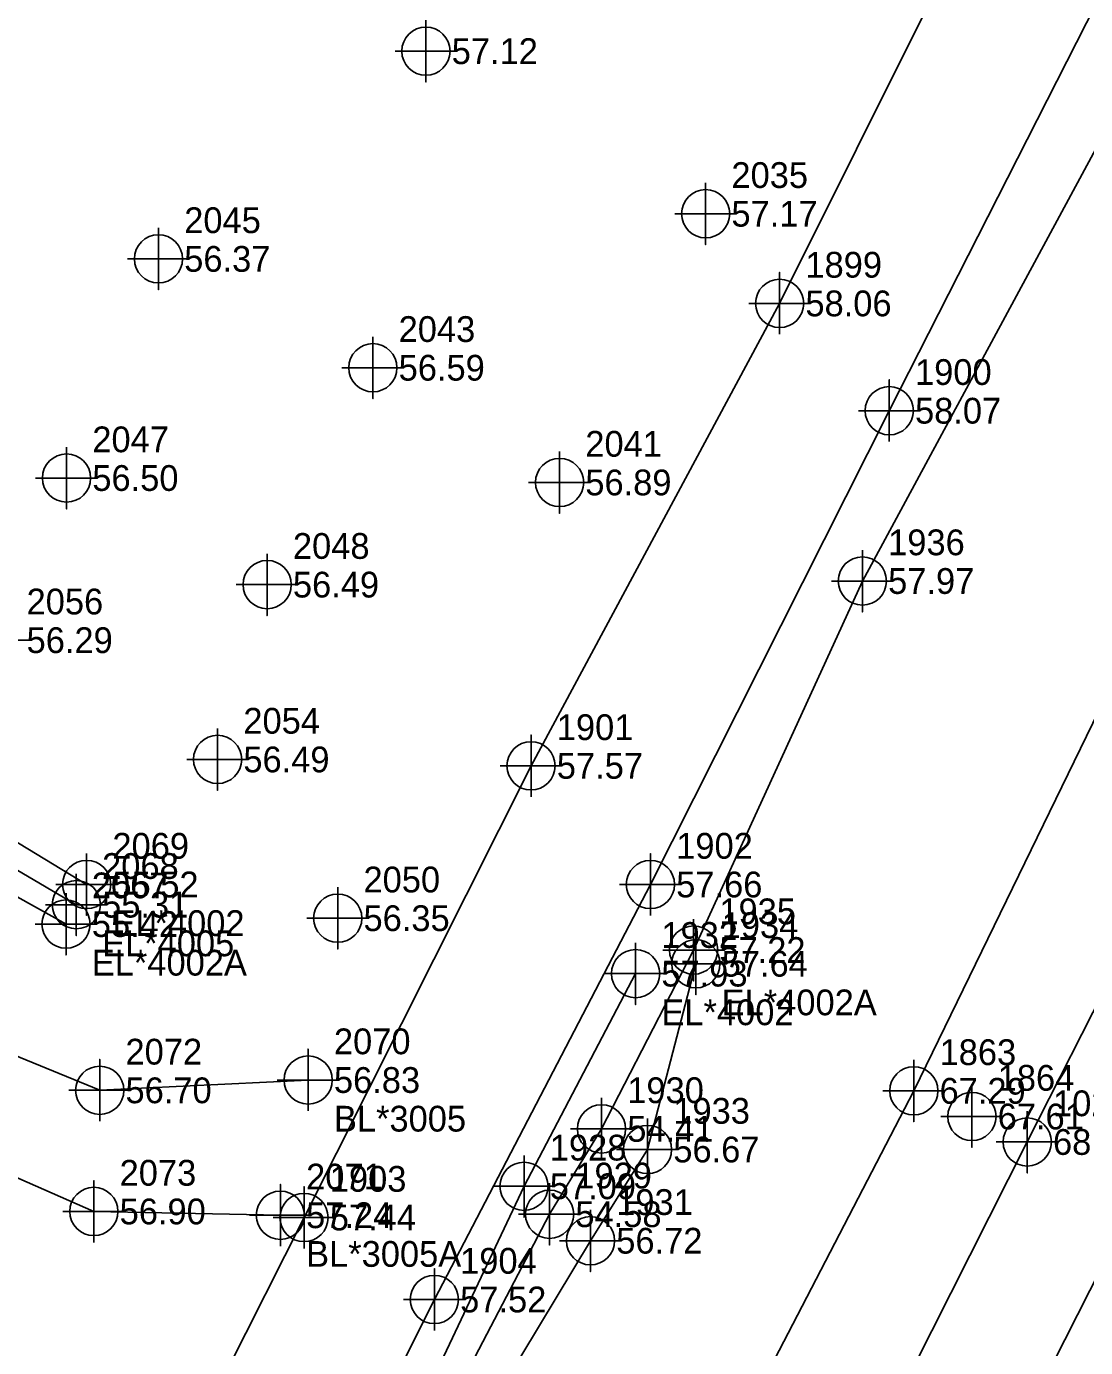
# Model space of a CAD drawing. Extents: x 2062781 to 2066835, y 358981 to 366501.
# Drawn here: x 2065986.1 to 2066088.9, y 365426.5 to 365554.7 of the extents above; entities that cross this region are included whole.
import ezdxf

# ---------------------------------------------------------------- set-up
doc = ezdxf.new("R2010")
doc.units = 0
for name, color, linetype in [('Exist DTM Breakline', 7, 'Continuous'), ('Exist DTM Breakline Cogo Comment', 7, 'Continuous'), ('Exist DTM Breakline Cogo Elevation', 7, 'Continuous'), ('Exist DTM Breakline Cogo Number', 7, 'Continuous'), ('Exist DTM Breakline Cogo Point CELL', 7, 'Continuous'), ('Exist DTM Crownline', 7, 'Continuous'), ('Exist DTM Regular Point CELL', 7, 'Continuous'), ('Exist DTM Regular Point Cogo Elevation', 7, 'Continuous'), ('Exist DTM Regular Point Cogo Number', 7, 'Continuous'), ('Exist DTM Ridgeline', 7, 'Continuous'), ('Exist DTM Ridgeline Cogo Comment', 7, 'Continuous'), ('Exist DTM Ridgeline Cogo Elevation', 7, 'Continuous'), ('Exist DTM Ridgeline Cogo Number', 7, 'Continuous'), ('Exist DTM Ridgeline Cogo Point CELL', 7, 'Continuous'), ('Exist Roads EOP', 7, 'Continuous'), ('Exist Roads EOP Cogo Elevation', 7, 'Continuous'), ('Exist Roads EOP Cogo Number', 7, 'Continuous'), ('Exist Roads EOP Cogo Point CELL', 7, 'Continuous'), ('Exist Roads Soil', 7, 'Continuous'), ('Exist Roads Soil Cogo Comment', 7, 'Continuous'), ('Exist Roads Soil Cogo Elevation', 7, 'Continuous'), ('Exist Roads Soil Cogo Number', 7, 'Continuous'), ('Exist Roads Soil Cogo Point CELL', 7, 'Continuous')]:
    doc.layers.add(name, color=color, linetype=linetype)

msp = doc.modelspace()

# ---------------------------------------------------------------- linework, layer by layer
at = {"layer": 'Exist DTM Breakline'}
for points in [[(2065868.05, 365108.36), (2065887.64, 365147.12), (2065915.95, 365200.53), (2065942.89, 365253.9), (2065967.73, 365303.79), (2065993.42, 365356.29), (2066016.32, 365400.12), (2066036.88, 365439.43), (2066041.92, 365447.71), (2066050.86, 365465.06), (2066067.24, 365500.86), (2066099.12, 365559.9), (2066123.36, 365605.47), (2066146.63, 365650.17), (2066168.17, 365694.53), (2066191.6, 365739.7), (2066213.66, 365782.56), (2066222.79, 365799.42), (2066244.31, 365840.96), (2066263.98, 365879.71), (2066274.73, 365899.77), (2066289.91, 365926.14)], [(2065855.04, 365022.37), (2065881.96, 365075.62), (2065912.8, 365134.88), (2065934.54, 365180.29), (2065958.76, 365228.22), (2065982.22, 365275.67), (2066005.39, 365319.97), (2066028.56, 365365.33), (2066047.41, 365403.57), (2066072.23, 365451.4), (2066094.41, 365496.9), (2066117.74, 365542.01), (2066140.9, 365588.6), (2066164.03, 365634.27), (2066187.25, 365680.45), (2066209.45, 365725.39), (2066232.88, 365773.48), (2066256.9, 365819.9), (2066281.9, 365870.6), (2066303.63, 365917.65)], [(2065895.39, 365509.68), (2065934.04, 365494.91), (2065965.95, 365484.13), (2065990.95, 365469.46)]]:
    msp.add_lwpolyline(points, dxfattribs=at)
at = {"layer": 'Exist DTM Breakline Cogo Point CELL'}
for points in [[(2066067.24, 365503.86), (2066067.24, 365497.86), (2066067.24, 365500.86), (2066070.24, 365500.86), (2066064.24, 365500.86)], [(2065990.95, 365472.46), (2065990.95, 365466.46), (2065990.95, 365469.46), (2065993.95, 365469.46), (2065987.95, 365469.46)], [(2066050.86, 365468.06), (2066050.86, 365462.06), (2066050.86, 365465.06), (2066053.86, 365465.06), (2066047.86, 365465.06)], [(2066072.23, 365454.4), (2066072.23, 365448.4), (2066072.23, 365451.4), (2066075.23, 365451.4), (2066069.23, 365451.4)], [(2066041.92, 365450.71), (2066041.92, 365444.71), (2066041.92, 365447.71), (2066044.92, 365447.71), (2066038.92, 365447.71)], [(2066036.88, 365442.43), (2066036.88, 365436.43), (2066036.88, 365439.43), (2066039.88, 365439.43), (2066033.88, 365439.43)]]:
    msp.add_lwpolyline(points, dxfattribs=at)
for centre in [(2066067.24, 365500.86), (2065990.95, 365469.46), (2066050.86, 365465.06), (2066072.23, 365451.4), (2066041.92, 365447.71), (2066036.88, 365439.43)]:
    msp.add_circle(centre, 2.34, dxfattribs=at)
at = {"layer": 'Exist DTM Crownline'}
msp.add_lwpolyline([(2066259.93, 365768.45), (2066236.46, 365721.83), (2066212.74, 365674.94), (2066188.43, 365627.04), (2066165.89, 365582.58), (2066140.87, 365533.44), (2066118.2, 365488.77), (2066092.94, 365439.19), (2066070.01, 365393.95), (2066043.74, 365342.11), (2066018.93, 365293.26), (2065993.67, 365243.42), (2065971.81, 365200.42), (2065946.33, 365150.52), (2065922.58, 365103.71), (2065905.53, 365070.58)], dxfattribs=at)
at = {"layer": 'Exist DTM Regular Point CELL'}
for points in [[(2066024.88, 365555.26), (2066024.88, 365549.26), (2066024.88, 365552.26), (2066027.88, 365552.26), (2066021.88, 365552.26)], [(2066052.03, 365539.49), (2066052.03, 365533.49), (2066052.03, 365536.49), (2066055.03, 365536.49), (2066049.03, 365536.49)], [(2065998.92, 365535.11), (2065998.92, 365529.11), (2065998.92, 365532.11), (2066001.92, 365532.11), (2065995.92, 365532.11)], [(2066019.73, 365524.55), (2066019.73, 365518.55), (2066019.73, 365521.55), (2066022.73, 365521.55), (2066016.73, 365521.55)], [(2065990, 365513.85), (2065990, 365507.85), (2065990, 365510.85), (2065993, 365510.85), (2065987, 365510.85)], [(2066037.85, 365513.42), (2066037.85, 365507.42), (2066037.85, 365510.42), (2066040.85, 365510.42), (2066034.85, 365510.42)], [(2066009.47, 365503.51), (2066009.47, 365497.51), (2066009.47, 365500.51), (2066012.47, 365500.51), (2066006.47, 365500.51)], [(2065983.62, 365498.12), (2065983.62, 365492.12), (2065983.62, 365495.12), (2065986.62, 365495.12), (2065980.62, 365495.12)], [(2066004.66, 365486.55), (2066004.66, 365480.55), (2066004.66, 365483.55), (2066007.66, 365483.55), (2066001.66, 365483.55)], [(2066016.32, 365471.15), (2066016.32, 365465.15), (2066016.32, 365468.15), (2066019.32, 365468.15), (2066013.32, 365468.15)], [(2066077.87, 365451.91), (2066077.87, 365445.91), (2066077.87, 365448.91), (2066080.87, 365448.91), (2066074.87, 365448.91)]]:
    msp.add_lwpolyline(points, dxfattribs=at)
for centre in [(2066024.88, 365552.26), (2066052.03, 365536.49), (2065998.92, 365532.11), (2066019.73, 365521.55), (2065990, 365510.85), (2066037.85, 365510.42), (2066009.47, 365500.51), (2066004.66, 365483.55), (2066016.32, 365468.15), (2066077.87, 365448.91)]:
    msp.add_circle(centre, 2.34, dxfattribs=at)
at = {"layer": 'Exist DTM Ridgeline'}
for points in [[(2065896.55, 365512.77), (2065935.26, 365497.88), (2065967.48, 365486.27), (2065991.95, 365471.42)], [(2065894.06, 365507.4), (2065932.67, 365492.47), (2065964.77, 365481.59), (2065989.95, 365467.58)], [(2066019.16, 365400.82), (2066040.85, 365436.86), (2066046.39, 365445.71), (2066051.08, 365463.73)], [(2066015.75, 365402.66), (2066034.4, 365442.14), (2066045.23, 365462.77)]]:
    msp.add_lwpolyline(points, dxfattribs=at)
at = {"layer": 'Exist DTM Ridgeline Cogo Point CELL'}
for points in [[(2065991.95, 365474.42), (2065991.95, 365468.42), (2065991.95, 365471.42), (2065994.95, 365471.42), (2065988.95, 365471.42)], [(2065989.95, 365470.58), (2065989.95, 365464.58), (2065989.95, 365467.58), (2065992.95, 365467.58), (2065986.95, 365467.58)], [(2066051.08, 365466.73), (2066051.08, 365460.73), (2066051.08, 365463.73), (2066054.08, 365463.73), (2066048.08, 365463.73)], [(2066045.23, 365465.77), (2066045.23, 365459.77), (2066045.23, 365462.77), (2066048.23, 365462.77), (2066042.23, 365462.77)], [(2066046.39, 365448.71), (2066046.39, 365442.71), (2066046.39, 365445.71), (2066049.39, 365445.71), (2066043.39, 365445.71)], [(2066034.4, 365445.14), (2066034.4, 365439.14), (2066034.4, 365442.14), (2066037.4, 365442.14), (2066031.4, 365442.14)], [(2066040.85, 365439.86), (2066040.85, 365433.86), (2066040.85, 365436.86), (2066043.85, 365436.86), (2066037.85, 365436.86)]]:
    msp.add_lwpolyline(points, dxfattribs=at)
for centre in [(2065991.95, 365471.42), (2065989.95, 365467.58), (2066051.08, 365463.73), (2066045.23, 365462.77), (2066046.39, 365445.71), (2066034.4, 365442.14), (2066040.85, 365436.86)]:
    msp.add_circle(centre, 2.34, dxfattribs=at)
at = {"layer": 'Exist Roads EOP'}
msp.add_lwpolyline([(2065895.47, 365076.64), (2065912.52, 365110.74), (2065936.33, 365156.98), (2065961.28, 365206.57), (2065984.24, 365251.56), (2066009, 365300.19), (2066033.36, 365348.17), (2066059.15, 365398.75), (2066083.24, 365446.44), (2066108.75, 365496.71), (2066129.9, 365538.17), (2066155.81, 365588.96), (2066178.82, 365634.51), (2066203.21, 365682.83), (2066225.78, 365727.06), (2066250.38, 365775.43)], dxfattribs=at)
at = {"layer": 'Exist Roads EOP Cogo Point CELL'}
msp.add_lwpolyline([(2066083.24, 365449.44), (2066083.24, 365443.44), (2066083.24, 365446.44), (2066086.24, 365446.44), (2066080.24, 365446.44)], dxfattribs=at)
msp.add_circle((2066083.24, 365446.44), 2.34, dxfattribs=at)
at = {"layer": 'Exist Roads Soil'}
for points in [[(2066215.29, 365839.32), (2066193.73, 365794.71), (2066173.36, 365754.82), (2066151.9, 365712.15), (2066128.57, 365664.45), (2066106.14, 365619.43), (2066081.59, 365572.67), (2066059.21, 365527.79), (2066035.08, 365482.93), (2066013.05, 365439.11), (2065990.46, 365394.28), (2065968.89, 365350.32), (2065945.11, 365301.86), (2065924.05, 365258.93), (2065901.5, 365213.37), (2065875.73, 365164.13), (2065851.89, 365115.26)], [(2066231.09, 365831.39), (2066206.91, 365786.4), (2066187.29, 365747.66), (2066165.8, 365703.86), (2066142.43, 365657.92), (2066118.99, 365612.17), (2066093.77, 365564.44), (2066069.85, 365517.38), (2066046.67, 365471.42), (2066025.7, 365431.16), (2066001.37, 365382.58), (2065980.65, 365340.33), (2065956.3, 365292.54), (2065935.55, 365249.64), (2065912.26, 365204.19), (2065886.05, 365154.3), (2065862.37, 365109.95)], [(2066013.45, 365452.45), (2065993.22, 365451.45), (2065972.54, 365459.95), (2065946.98, 365473.12), (2065914.21, 365485.56), (2065905.26, 365485.9)], [(2066010.75, 365439.33), (2065992.65, 365439.7), (2065966.43, 365451.21), (2065939.03, 365464.2), (2065910.17, 365474.04), (2065899.23, 365477.26)]]:
    msp.add_lwpolyline(points, dxfattribs=at)
at = {"layer": 'Exist Roads Soil Cogo Point CELL'}
for points in [[(2066059.21, 365524.79), (2066059.21, 365530.79), (2066059.21, 365527.79), (2066062.21, 365527.79), (2066056.21, 365527.79)], [(2066069.85, 365514.38), (2066069.85, 365520.38), (2066069.85, 365517.38), (2066072.85, 365517.38), (2066066.85, 365517.38)], [(2066035.08, 365479.93), (2066035.08, 365485.93), (2066035.08, 365482.93), (2066038.08, 365482.93), (2066032.08, 365482.93)], [(2066046.67, 365468.42), (2066046.67, 365474.42), (2066046.67, 365471.42), (2066049.67, 365471.42), (2066043.67, 365471.42)], [(2065993.22, 365448.45), (2065993.22, 365454.45), (2065993.22, 365451.45), (2065996.22, 365451.45), (2065990.22, 365451.45)], [(2066013.45, 365449.45), (2066013.45, 365455.45), (2066013.45, 365452.45), (2066016.45, 365452.45), (2066010.45, 365452.45)], [(2065992.65, 365436.7), (2065992.65, 365442.7), (2065992.65, 365439.7), (2065995.65, 365439.7), (2065989.65, 365439.7)], [(2066010.75, 365436.33), (2066010.75, 365442.33), (2066010.75, 365439.33), (2066013.75, 365439.33), (2066007.75, 365439.33)], [(2066013.05, 365436.11), (2066013.05, 365442.11), (2066013.05, 365439.11), (2066016.05, 365439.11), (2066010.05, 365439.11)], [(2066025.7, 365428.16), (2066025.7, 365434.16), (2066025.7, 365431.16), (2066028.7, 365431.16), (2066022.7, 365431.16)]]:
    msp.add_lwpolyline(points, dxfattribs=at)
for centre in [(2066059.21, 365527.79), (2066069.85, 365517.38), (2066035.08, 365482.93), (2066046.67, 365471.42), (2066013.45, 365452.45), (2065993.22, 365451.45), (2065992.65, 365439.7), (2066010.75, 365439.33), (2066013.05, 365439.11), (2066025.7, 365431.16)]:
    msp.add_circle(centre, 2.34, dxfattribs=at)

# ---------------------------------------------------------------- texts
at = {"layer": 'Exist DTM Breakline Cogo Comment'}
msp.add_text('EL*4005', height=2.5, dxfattribs=at).set_placement((2065993.45, 365464.46))
at = {"layer": 'Exist DTM Breakline Cogo Elevation'}
for s, p in [('57.97', (2066069.74, 365499.61)), ('55.31', (2065993.45, 365468.21)), ('57.22', (2066053.36, 365463.81)), ('67.29', (2066074.73, 365450.15)), ('54.41', (2066044.42, 365446.46)), ('54.58', (2066039.38, 365438.18))]:
    msp.add_text(s, height=2.5, dxfattribs=at).set_placement(p)
at = {"layer": 'Exist DTM Breakline Cogo Number'}
for s, p in [('1936', (2066069.74, 365503.36)), ('2068', (2065993.45, 365471.96)), ('1935', (2066053.36, 365467.56)), ('1863', (2066074.73, 365453.9)), ('1930', (2066044.42, 365450.21)), ('1929', (2066039.38, 365441.93))]:
    msp.add_text(s, height=2.5, dxfattribs=at).set_placement(p)
at = {"layer": 'Exist DTM Regular Point Cogo Elevation'}
for s, p in [('57.12', (2066027.38, 365551.01)), ('57.17', (2066054.53, 365535.24)), ('56.37', (2066001.42, 365530.86)), ('56.59', (2066022.23, 365520.3)), ('56.50', (2065992.5, 365509.6)), ('56.89', (2066040.35, 365509.17)), ('56.49', (2066011.97, 365499.26)), ('56.29', (2065986.12, 365493.87)), ('56.49', (2066007.16, 365482.3)), ('56.35', (2066018.82, 365466.9)), ('67.61', (2066080.37, 365447.66))]:
    msp.add_text(s, height=2.5, dxfattribs=at).set_placement(p)
at = {"layer": 'Exist DTM Regular Point Cogo Number'}
for s, p in [('2035', (2066054.53, 365538.99)), ('2045', (2066001.42, 365534.61)), ('2043', (2066022.23, 365524.05)), ('2047', (2065992.5, 365513.35)), ('2041', (2066040.35, 365512.92)), ('2048', (2066011.97, 365503.01)), ('2056', (2065986.12, 365497.62)), ('2054', (2066007.16, 365486.05)), ('2050', (2066018.82, 365470.65)), ('1864', (2066080.37, 365451.41))]:
    msp.add_text(s, height=2.5, dxfattribs=at).set_placement(p)
at = {"layer": 'Exist DTM Ridgeline Cogo Comment'}
for s, p in [('EL*4002', (2065994.45, 365466.42)), ('EL*4002A', (2065992.45, 365462.58)), ('EL*4002A', (2066053.58, 365458.73)), ('EL*4002', (2066047.73, 365457.77))]:
    msp.add_text(s, height=2.5, dxfattribs=at).set_placement(p)
at = {"layer": 'Exist DTM Ridgeline Cogo Elevation'}
for s, p in [('55.52', (2065994.45, 365470.17)), ('55.42', (2065992.45, 365466.33)), ('57.64', (2066053.58, 365462.48)), ('57.93', (2066047.73, 365461.52)), ('56.67', (2066048.89, 365444.46)), ('57.09', (2066036.9, 365440.89)), ('56.72', (2066043.35, 365435.61))]:
    msp.add_text(s, height=2.5, dxfattribs=at).set_placement(p)
at = {"layer": 'Exist DTM Ridgeline Cogo Number'}
for s, p in [('2069', (2065994.45, 365473.92)), ('2067', (2065992.45, 365470.08)), ('1934', (2066053.58, 365466.23)), ('1932', (2066047.73, 365465.27)), ('1933', (2066048.89, 365448.21)), ('1928', (2066036.9, 365444.64)), ('1931', (2066043.35, 365439.36))]:
    msp.add_text(s, height=2.5, dxfattribs=at).set_placement(p)
at = {"layer": 'Exist Roads EOP Cogo Elevation'}
msp.add_text('68.33', height=2.5, dxfattribs=at).set_placement((2066085.74, 365445.19))
at = {"layer": 'Exist Roads EOP Cogo Number'}
msp.add_text('1021', height=2.5, dxfattribs=at).set_placement((2066085.74, 365448.94))
at = {"layer": 'Exist Roads Soil Cogo Comment'}
for s, p in [('BL*3005', (2066015.95, 365447.45)), ('BL*3005A', (2066013.25, 365434.33))]:
    msp.add_text(s, height=2.5, dxfattribs=at).set_placement(p)
at = {"layer": 'Exist Roads Soil Cogo Elevation'}
for s, p in [('58.06', (2066061.71, 365526.54)), ('58.07', (2066072.35, 365516.13)), ('57.57', (2066037.58, 365481.68)), ('57.66', (2066049.17, 365470.17)), ('56.83', (2066015.95, 365451.2)), ('56.70', (2065995.72, 365450.2)), ('56.90', (2065995.15, 365438.45)), ('57.24', (2066013.25, 365438.08)), ('57.44', (2066015.55, 365437.86)), ('57.52', (2066028.2, 365429.91))]:
    msp.add_text(s, height=2.5, dxfattribs=at).set_placement(p)
at = {"layer": 'Exist Roads Soil Cogo Number'}
for s, p in [('1899', (2066061.71, 365530.29)), ('1900', (2066072.35, 365519.88)), ('1901', (2066037.58, 365485.43)), ('1902', (2066049.17, 365473.92)), ('2070', (2066015.95, 365454.95)), ('2072', (2065995.72, 365453.95)), ('2073', (2065995.15, 365442.2)), ('2071', (2066013.25, 365441.83)), ('1903', (2066015.55, 365441.61)), ('1904', (2066028.2, 365433.66))]:
    msp.add_text(s, height=2.5, dxfattribs=at).set_placement(p)

doc.saveas('drawing.dxf')
